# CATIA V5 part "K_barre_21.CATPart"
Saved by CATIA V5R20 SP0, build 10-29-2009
Part number: barre 21
Publications: "demi largeur balancier", "epaisseur pieces", "Plan.00", "liaison 10/21", "liaison 21/28", "liaison 21/74 sur 21"
Bounding box of the stored display mesh (mm): x -30 to 45, y -935 to 175, z 420 to 525
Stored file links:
  G:\Khaled_CFAO_2011\SIL\SIL_GR2\mdardier\Khaled\CAD_ThinkMOTION\K_barre_21.CATPart
  G:\Khaled_CFAO_2011\SIL\SIL_GR2\mdardier\Khaled\CAD_ThinkMOTION\K_ass_tandem.CATProduct
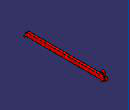
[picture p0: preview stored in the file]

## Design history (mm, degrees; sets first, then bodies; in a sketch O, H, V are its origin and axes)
External parameters (linked from other documents)
  `External.demi largeur balancier` = 50 mm
  `External.epaisseur pieces` = 30 mm
Set1
  Plane1 "Plan.00": linked copy from another document
  Point1 "liaison 10/21": linked copy from another document
  Point2 "liaison 21/28": linked copy from another document
  Point3 "liaison 21/74 sur 21": linked copy from another document
Set2
  Boundary1: Boundary face of Pad1 from Sketch1.A4
  Extract1: ExtractElem edge of Boundary1
  Boundary2: Boundary face of Pad1 from Sketch1.A6
  Extract2: ExtractElem edge of Boundary2
Body1 (main body)
  Sketch1 on Plane1, origin (0, 0, 0), H (0, 1, 0), V (0, 0, 1)
    construction line L1 (-910, 445) -> (150, 445)
    point P1 (-910, 445)
    point P2 (150, 445)
    line L2 (-910, 470) -> (90, 470)
    line L3 (150, 420) -> (-910, 420)
    arc A1 centre (150, 445) radius 25 from (150, 470) to (150, 420) cw
    arc A2 centre (-910, 445) radius 25 from (-910, 420) to (-910, 470) cw
    reference projected point E1 (-910, 445) from Point1
    reference projected point E2 (150, 445) from Point2
    arc A3 centre (115, 500) radius 25 from (140, 500) to (90, 500) ccw
    point P7 (115, 500)
    reference projected point E3 (115, 500) from Point3
    line L4 (90, 500) -> (90, 470)
    line L5 (140, 500) -> (140, 470)
    point P11 (140, 470)
    line L6 (140, 470) -> (150, 470)
    circle A4 centre (-910, 445) radius 12.5
    point P12 (-910, 445)
    reference projected point E4 (-910, 445) from Point1
    circle A5 centre (115, 500) radius 12.5
    point P13 (115, 500)
    reference projected point E5 (115, 500) from Point3
    circle A6 centre (150, 445) radius 12.5
    point P14 (150, 445)
    reference projected point E6 (150, 445) from Point2
    distance L1 L2 = 25 {= `External.demi largeur balancier` /2}
    radius A3 = 25 {= `External.demi largeur balancier` /2}
    radius A4 = 12.5 {= `External.demi largeur balancier` /4}
    radius A5 = 12.5 {= `External.demi largeur balancier` /4}
    radius A6 = 12.5 {= `External.demi largeur balancier` /4}
    tangency: A1 L2, A2 L2, A1 L3, A2 L3, L4 A3, L5 A3
    coincidence: P1 E1, P2 E2, P7 E3, P11 L2, L2 L6, P12 E4, P13 E5, P14 E6
    perpendicularity: L4 L2, L5 L2
  Pad1: profile Sketch1, direction (-1, 0, 0), length 30 {= `External.epaisseur pieces`}
  Pad2: profile Extract1, length 45
  Fillet1: radius 10, on edge [end face of Pad2 | face of Pad2]
  Pad3: profile Extract2, length 45
  Fillet2: radius 10, on end face of Pad3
